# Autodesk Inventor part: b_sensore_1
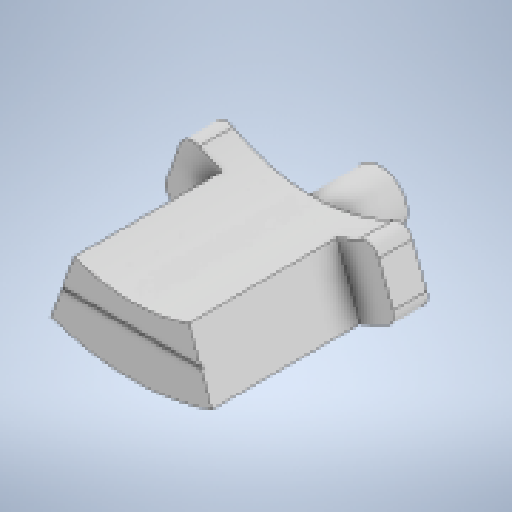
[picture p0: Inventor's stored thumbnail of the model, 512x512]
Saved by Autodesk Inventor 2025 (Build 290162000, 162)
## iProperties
Created: 2026-03
Part Number: b_sensore_1
Material: Generico
Document SubType Name: Modeling
Designer: Ryzen5700u
Density: 1 g/cm^3
Appearance: Default
Author: Ryzen5700u
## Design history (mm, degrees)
sketch "Schizzo1" dims "d0" = 70
  geometry: L1 (0, 0)-(-11.971, -32.889); L2 (0, 0)-(35, 0); L3 (0, 0)-(0, 45.813); L4 (0, 0)-(11.971, -32.889); L5 (-5.638, 2.052)-(-17.609, -30.837); L6 (5.615, 2.115)-(17.586, -30.775); L7 (0, 0)-(0, -30); C1 r 25 at (0, 0); C2 r 4 at (0, -30); 9 further points
  constraints: 14 end point, 3 coincident, 2 centre point, 2 parallel, 2 vertical, 1 equal length, 1 horizontal, 1 symmetric about line, 3 other
  dimensions: "d1" = 50 diameter of C1; "d2" = 110 deg angle of L1 L2; "d5" = 6 distance between parallel lines of L1 L5; "d6" = 6 distance between parallel lines of L4 L6; "d10" = 30 distance of L1.start L7.end; "d11" = 8 diameter of C2
extrude "Estrusione1" new body sketch "Schizzo1" distance "d3" = 27; taper "d4" = 0 deg
extrude "Estrusione2" join sketch "Schizzo1" distance "d7" = 5; taper "d8" = 0 deg
fillet "Raccordo1" dims "d9" = 2
extrude "Estrusione3" join sketch "Schizzo1" distance "d12" = 10; taper "d13" = 0 deg
sketch "Schizzo2"
  geometry: L1 (-8.551, -23.492)-(-11.971, -32.889) reference; L2 (-10.261, -28.191)-(10.261, -28.191); L3 (11.971, -32.889)-(8.551, -23.492) reference; L4 (-10.406, -28.591)-(10.406, -28.591); L5 (-8.551, -23.492)-(-11.971, -32.889) reference; L6 (11.971, -32.889)-(8.551, -23.492) reference; A1 r 25 centre (0, 0) between (-8.551, -23.492) and (8.551, -23.492) reference; A2 r 35 centre (0, 0) between (-11.971, -32.889) and (11.971, -32.889) reference; 3 further points
  constraints: 4 end point, 2 midpoint, 2 point on line, 1 parallel
  dimensions: "d14" = 0.4 distance between parallel lines of L2 L4
extrude "Estrusione4" cut sketch "Schizzo2" distance "d15" = 0.2; taper "d16" = 0 deg
node "Solido1"
node "Linea chiusa proiettata1"
